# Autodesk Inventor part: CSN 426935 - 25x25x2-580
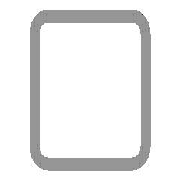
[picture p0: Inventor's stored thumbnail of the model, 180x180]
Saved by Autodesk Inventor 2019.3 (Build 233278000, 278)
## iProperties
Created: 2018-01
Part Number: CSN 426935 - 25x25x2-580
Material: Ocel, měkká
Description: Tenkostěnné profily ocelové svařované (čtvercový profil)
Document SubType Name: Modellieren
Standard: CSN 42 6935
Designer: B-hon
Standards Organization: CSN
Language: cs-CZ
Size Designation: 25x25x2-580
Categories: <MemberInstance><Categories><Category DisplayName="Konstrukční profily" InternalName="089c4875-fa83-4c05-b084-43b9cc11f5ed" Mnemonic="GRDR"><CategoryParameter D
Stock Number: 25x25x2
Density: 7.85 g/cm^3
Appearance: Pololeštěná
G_L: 580,000 mm
IsCustomPart: 1
Author: B-hon
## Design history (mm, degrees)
node "Počáteční rovina"
node "Koncová rovina"
sketch "Náčrt1"
  geometry: L1 (-8.5, 12.5)-(8.5, 12.5); L2 (12.5, 8.5)-(12.5, -8.5); L3 (8.5, -12.5)-(-8.5, -12.5); L4 (-12.5, -8.5)-(-12.5, 8.5); L5 (-21.87, 0)-(21.87, 0) reference; L6 (0, -21.87)-(0, 21.87) reference; L7 (-8.5, 10.5)-(8.5, 10.5); L8 (10.5, 8.5)-(10.5, -8.5); L9 (8.5, -10.5)-(-8.5, -10.5); L10 (-10.5, -8.5)-(-10.5, 8.5); A1 r 4 centre (-8.5, 8.5) between (-8.5, 12.5) and (-12.5, 8.5); A2 r 4 centre (8.5, 8.5) between (12.5, 8.5) and (8.5, 12.5); A3 r 4 centre (8.5, -8.5) between (8.5, -12.5) and (12.5, -8.5); A4 r 4 centre (-8.5, -8.5) between (-12.5, -8.5) and (-8.5, -12.5); A5 r 2 centre (-8.5, 8.5) between (-8.5, 10.5) and (-10.5, 8.5); A6 r 2 centre (8.5, 8.5) between (10.5, 8.5) and (8.5, 10.5); A7 r 2 centre (8.5, -8.5) between (8.5, -10.5) and (10.5, -8.5); A8 r 2 centre (-8.5, -8.5) between (-10.5, -8.5) and (-8.5, -10.5); 3 further points
  constraints: 16 end point, 16 point on circle, 8 centre point, 8 tangent, 6 point on line, 4 parallel, 3 equal radius, 3 perpendicular, 1 horizontal, 7 other
  dimensions: "b" = 25 distance of point (-12.5, 12.5) point (12.5, 12.5); "msp_r" = 4 radius of A1 (= 2 x ParT); "d8" = 12.5 distance between parallel lines of L4 L6 (= d9); "d9" = 12.5 distance between parallel lines of L3 L5 (= 0.5 x b); "d10" = 2 distance between parallel lines of L3 L9 (= ParT)
extrude "Těleso" new body sketch "Náčrt1" taper "d4" = 0 deg; stored distance "NLG" = 10
node "Driven Length"
  sketch "Sketch2"
    geometry: L1 (0, 0)-(10, 0) reference
    constraints: 2 end point, 1 horizontal
  workplane "Work Plane3"
  sketch "Sketch3"
    geometry: L1 (-2, 0)-(12, 0) reference; L2 (-2, 580)-(12, 580) reference
    dimensions: "d14" = 580 distance between parallel lines of L1 L2 (derived)
sketch "Náčrt4"
  geometry: L1 (22.851, 584.797)-(-12.019, 560.381); L2 (-12.019, 560.381)-(-17.193, 582.063); L3 (-17.193, 582.063)-(22.851, 584.797); L4 (17, 580)-(0, 580) reference; L5 (0, 580)-(17, 580) reference; L6 (21, 0)-(21, 580) reference; L7 (26.327, -7.231)-(-6.728, 15.914); L8 (-6.728, 15.914)-(-10.46, -11.056); L9 (-10.46, -11.056)-(26.327, -7.231); L10 (17, 0)-(0, 0) reference; 3 further points
  constraints: 12 end point, 4 point on line
  dimensions: "d15" = 5 distance from line of L6 point (16, 580); "d16" = 55 deg angle of L6 L1; "d17" = 5 distance from line of L6 point (16, 0); "d18" = 55 deg angle of L7 L6
extrude "Vysunutí2" cut sketch "Náčrt4" distance "d19" = 30; taper "d20" = 0 deg
sketch "Náčrt5"
  geometry: L1 (-1, 580)-(-17, 568.797) reference; L2 (-17, 11.203)-(-17, 568.797) reference; L3 (-17, 11.203)-(-1, 0) reference; L4 (0, 0)-(-1, 0) reference; L5 (0, 0)-(0, 580) reference; L6 (0, 580)-(-1, 580) reference; C1 r 5 at (-7, 22.5); C2 r 5 at (-7, 557.5); 4 further points
  constraints: 2 centre point, 2 coincident, 1 vertical alignment
  dimensions: "d21" = 10 diameter of C1; "d22" = 2 distance edge to line of C1 L5; "d24" = 2 distance edge to line of C2 L5; "d27" = 10 diameter of C2; "d29" = 535 distance of point (-7, 22.5) point (-7, 557.5); "d30" = 580 distance of L4.start L5.end (derived); "d31" = 22.5 vertical distance of L4.start point (-7, 22.5) (= -0.5 x d29 + 0.5 x d30); "d32" = 267.5 distance of point (-7, 290) point (-7, 22.5) (= 0.5 x d29)
hole "Díra1" sketch "Náčrt5" at (-7, 22.5), (-7, 557.5), (-7, 290) diameter "d33" = 5.5; stored, may be unused: countersink angle "d37" = 90 deg, drill point angle "d39" = 118 deg; dims "d34" = 6, "d35" = 4, "d36" = 2, "d38" = 8
sketch "Náčrt6"
  geometry: L1 (580, 21)-(0, 21) reference; L2 (0, 17)-(0, 0) reference; 3 further points
  constraints: 1 horizontal alignment
  dimensions: "d40" = 12.5 distance from line of point (314.5, 8.5) L1; "d41" = 49 distance of point (265.5, 8.5) point (314.5, 8.5); "d42" = 580 distance of L1.start L1.end (derived); "d43" = 265.5 distance from line of L2 point (265.5, 8.5) (= -0.5 x d41 + 0.5 x d42)
hole "Díra2" sketch "Náčrt6" at (265.5, 8.5), (314.5, 8.5) diameter "d44" = 6.6; stored, may be unused: countersink angle "d48" = 90 deg, drill point angle "d50" = 118 deg; dims "d45" = 6, "d46" = 4, "d47" = 2, "d49" = 8
body "Solid1"
node "Promítnutá smyčka1"
other parameters: "ParT" = 2, "G_OFFSET_START" = 0 [user parameter; used in 1 equation term], "G_OFFSET_END" = 0 [user parameter; used in 1 equation term], "d11" = 0 (computed from G_OFFSET_START), "G_L" = 580 (= d14) [user parameter], "d13" = 90 deg, "sa_0" = 0, "sa_1" = -500000, "sa_2" = 0
